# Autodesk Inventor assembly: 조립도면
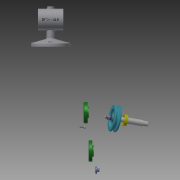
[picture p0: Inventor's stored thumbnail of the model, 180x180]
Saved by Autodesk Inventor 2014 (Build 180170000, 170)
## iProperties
Created: 2018-12
Part Number: 조립도면
Document SubType Name: Assembly
Designer: kh
Author: kh
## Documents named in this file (15)
- C:\Users\kh\Desktop\481207V1033\조립도면.iam
- C:\Users\kh\Desktop\481207V1033\본체.ipt
- C:\Users\kh\Desktop\481207V1033\V벨트풀리.ipt
- C:\Users\kh\Desktop\481207V1033\고무캡.ipt
- C:\Users\kh\Desktop\481207V1033\너트 M8.ipt
- 너트 M8.ipt
- C:\Users\kh\Desktop\481207V1033\뒤커버.ipt
- C:\Users\kh\Desktop\481207V1033\베어링 15 x 32 x 9.ipt
- C:\Users\kh\Desktop\481207V1033\볼트 M4 x 12.ipt
- C:\Users\kh\Desktop\481207V1033\스프링와셔 8.ipt
- C:\Users\kh\Desktop\481207V1033\앞커버.ipt
- C:\Users\kh\Desktop\481207V1033\오일 실 15 25 7.ipt
- C:\Users\kh\Desktop\481207V1033\와셔 8x17.ipt
- C:\Users\kh\Desktop\481207V1033\축.ipt
- C:\Users\kh\Desktop\481207V1033\키 3 x 3 x 12.ipt
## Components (2 placed, 2 different names)
1. V벨트풀리:1 — Insert:4, Mate:1, Insert:5
2. 고무캡:1
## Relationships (3: Insert 2, Mate 1)
- Insert:4: V벨트풀리:1
- Mate:1: V벨트풀리:1
- Insert:5: V벨트풀리:1
